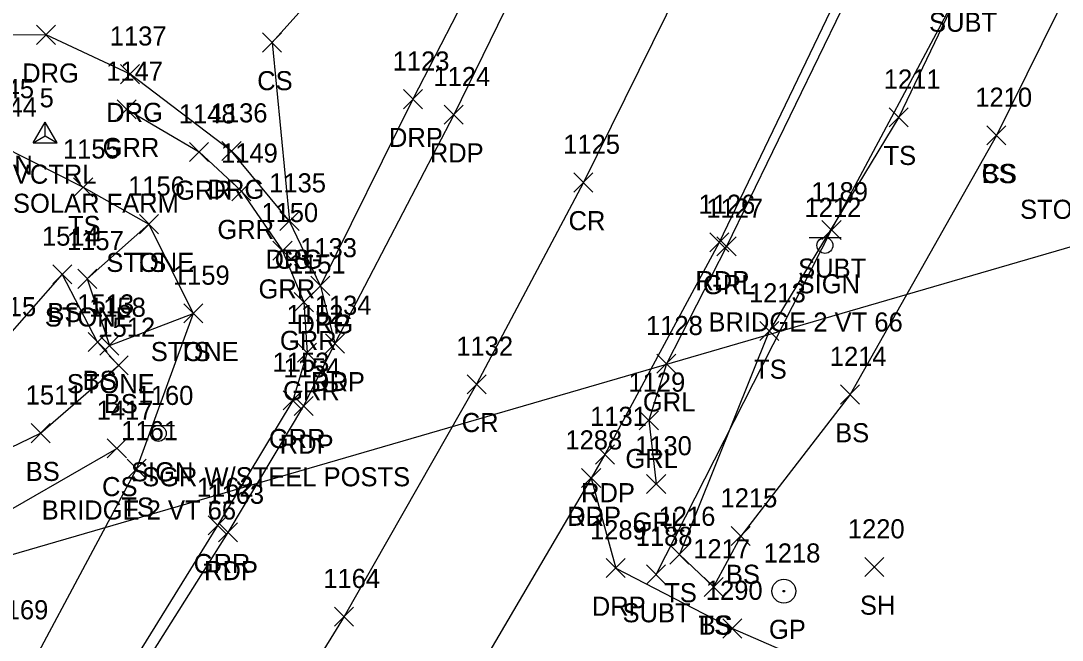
# Model space of a CAD drawing. Extents: x 1599840 to 1601211, y 518904 to 521989.
# Drawn here: x 1600815 to 1600924.1, y 521288.6 to 521353.5 of the extents above; entities that cross this region are included whole.
import ezdxf

# ---------------------------------------------------------------- set-up
doc = ezdxf.new("R2010")
doc.units = 0
for name, color, linetype in [('C_A', 7, 'Continuous'), ('C_I', 7, 'Continuous'), ('CPSM', 7, 'Continuous'), ('DCP', 7, 'Continuous'), ('L_A', 7, 'Continuous'), ('L_C', 7, 'Continuous'), ('L_I', 7, 'Continuous'), ('L_TIC', 7, 'Continuous'), ('LASF', 7, 'Continuous'), ('LELB', 7, 'Continuous'), ('P_A', 7, 'Continuous'), ('P_I', 7, 'Continuous'), ('P_TIC', 7, 'Continuous'), ('PET', 7, 'Continuous'), ('PRC', 7, 'Continuous'), ('R_A', 7, 'Continuous'), ('R_C', 7, 'Continuous'), ('R_I', 7, 'Continuous'), ('R_TIC', 7, 'Continuous'), ('RDG', 7, 'Continuous'), ('RDP', 7, 'Continuous'), ('RGP', 7, 'Continuous'), ('RGR', 7, 'Continuous'), ('S_A', 7, 'Continuous'), ('S_C', 7, 'Continuous'), ('S_I', 7, 'Continuous'), ('SSGN', 7, 'Continuous'), ('U_A', 7, 'Continuous'), ('U_I', 7, 'Continuous'), ('U_TIC', 7, 'Continuous'), ('UT', 7, 'Continuous')]:
    doc.layers.add(name, color=color, linetype=linetype)

msp = doc.modelspace()

# ---------------------------------------------------------------- linework, layer by layer
at = {"layer": 'CPSM'}
for p, q in [((1600816.3, 521340.7), (1600817.55, 521342.87)), ((1600818.8, 521340.7), (1600817.55, 521342.87)), ((1600817.55, 521341.42), (1600817.55, 521342.87)), ((1600816.3, 521340.7), (1600817.55, 521341.42)), ((1600817.55, 521341.42), (1600817.55, 521341.42)), ((1600817.55, 521341.42), (1600818.8, 521340.7)), ((1600816.3, 521340.7), (1600818.8, 521340.7))]:
    msp.add_line(p, q, dxfattribs=at)
at = {"layer": 'DCP'}
msp.add_lwpolyline([(1600954.73, 521338.43), (1600785.44, 521289.23)], dxfattribs=at)
at = {"layer": 'L_TIC'}
for points in [[(1600840.34, 521350.21), (1600842.34, 521352.21)], [(1600842.34, 521350.21), (1600840.34, 521352.21)], [(1600906.01, 521342.38), (1600908.01, 521344.38)], [(1600908.01, 521342.38), (1600906.01, 521344.38)], [(1600916.25, 521340.48), (1600918.25, 521342.48)], [(1600918.25, 521340.48), (1600916.25, 521342.48)], [(1600916.25, 521340.48), (1600918.25, 521342.48)], [(1600918.25, 521340.48), (1600916.25, 521342.48)], [(1600820.54, 521335.05), (1600822.54, 521337.05)], [(1600822.54, 521335.05), (1600820.54, 521337.05)], [(1600827.43, 521331.18), (1600829.43, 521333.18)], [(1600829.43, 521331.18), (1600827.43, 521333.18)], [(1600827.43, 521331.18), (1600829.43, 521333.18)], [(1600829.43, 521331.18), (1600827.43, 521333.18)], [(1600827.43, 521331.18), (1600829.43, 521333.18)], [(1600829.43, 521331.18), (1600827.43, 521333.18)], [(1600842.17, 521331.51), (1600844.17, 521333.51)], [(1600844.17, 521331.51), (1600842.17, 521333.51)], [(1600818.35, 521325.93), (1600820.35, 521327.93)], [(1600820.35, 521325.93), (1600818.35, 521327.93)], [(1600820.97, 521325.46), (1600822.97, 521327.46)], [(1600822.97, 521325.46), (1600820.97, 521327.46)], [(1600832.08, 521321.84), (1600834.08, 521323.84)], [(1600834.08, 521321.84), (1600832.08, 521323.84)], [(1600832.08, 521321.84), (1600834.08, 521323.84)], [(1600834.08, 521321.84), (1600832.08, 521323.84)], [(1600832.08, 521321.84), (1600834.08, 521323.84)], [(1600834.08, 521321.84), (1600832.08, 521323.84)], [(1600892.45, 521319.99), (1600894.45, 521321.99)], [(1600894.45, 521319.99), (1600892.45, 521321.99)], [(1600822.05, 521318.83), (1600824.05, 521320.83)], [(1600824.05, 521318.83), (1600822.05, 521320.83)], [(1600823.29, 521318.48), (1600825.29, 521320.48)], [(1600825.29, 521318.48), (1600823.29, 521320.48)], [(1600824.26, 521316.39), (1600826.26, 521318.39)], [(1600826.26, 521316.39), (1600824.26, 521318.39)], [(1600900.91, 521313.34), (1600902.91, 521315.34)], [(1600902.91, 521313.34), (1600900.91, 521315.34)], [(1600816.08, 521309.29), (1600818.08, 521311.29)], [(1600818.08, 521309.29), (1600816.08, 521311.29)], [(1600824.07, 521307.7), (1600826.07, 521309.7)], [(1600826.07, 521307.7), (1600824.07, 521309.7)], [(1600826.14, 521305.56), (1600828.14, 521307.56)], [(1600828.14, 521305.56), (1600826.14, 521307.56)], [(1600889.46, 521298.52), (1600891.46, 521300.52)], [(1600891.46, 521298.52), (1600889.46, 521300.52)], [(1600883.03, 521296.59), (1600885.03, 521298.59)], [(1600885.03, 521296.59), (1600883.03, 521298.59)], [(1600903.46, 521295.28), (1600905.46, 521297.28)], [(1600905.46, 521295.28), (1600903.46, 521297.28)], [(1600886.61, 521293.19), (1600888.61, 521295.19)], [(1600888.61, 521293.19), (1600886.61, 521295.19)], [(1600886.61, 521293.19), (1600888.61, 521295.19)], [(1600888.61, 521293.19), (1600886.61, 521295.19)]]:
    msp.add_lwpolyline(points, dxfattribs=at)
at = {"layer": 'LASF'}
for points in [[(1600828.43, 521332.18), (1600821.97, 521326.46), (1600824.29, 521319.48), (1600833.08, 521322.84)], [(1600828.43, 521332.18), (1600833.08, 521322.84)]]:
    msp.add_lwpolyline(points, dxfattribs=at)
at = {"layer": 'LELB'}
for points in [[(1600966.09, 521495.52), (1600959.78, 521473.28), (1600948.85, 521440.97), (1600941.09, 521418.3), (1600930.04, 521391.16), (1600917.79, 521365.83), (1600907.01, 521343.38), (1600893.45, 521320.99), (1600884.03, 521297.59), (1600887.61, 521294.19)], [(1600939.06, 521387.92), (1600926.77, 521360.7), (1600917.25, 521341.48)], [(1600849.45, 521360.23), (1600841.34, 521351.21), (1600843.17, 521332.51)], [(1600917.25, 521341.48), (1600901.91, 521314.34), (1600890.46, 521299.52), (1600887.61, 521294.19)], [(1600756.56, 521333.97), (1600770.61, 521339.96), (1600790.38, 521340.53), (1600812.86, 521340.45), (1600821.54, 521336.05), (1600828.43, 521332.18)], [(1600806.43, 521305.18), (1600817.08, 521310.29), (1600825.26, 521317.39), (1600823.05, 521319.83), (1600819.35, 521326.93), (1600812.8, 521319.54), (1600805.24, 521316.79)], [(1600833.08, 521322.84), (1600827.14, 521306.56), (1600810.92, 521276.32), (1600800.69, 521262.52), (1600794.58, 521254.04), (1600785.73, 521239.52), (1600767.25, 521213.82), (1600747.49, 521193.49), (1600721.35, 521163.12)], [(1600741.13, 521196.94), (1600761, 521225.76), (1600770.64, 521247.14), (1600790.98, 521265.75), (1600800.28, 521274.95), (1600804.56, 521287.9), (1600802.13, 521291.13), (1600804.08, 521295.26), (1600810.48, 521300.32), (1600825.07, 521308.7)]]:
    msp.add_lwpolyline(points, dxfattribs=at)
at = {"layer": 'P_TIC'}
for points in [[(1600859.38, 521342.64), (1600861.38, 521344.64)], [(1600861.38, 521342.64), (1600859.38, 521344.64)], [(1600872.97, 521335.55), (1600874.97, 521337.55)], [(1600874.97, 521335.55), (1600872.97, 521337.55)], [(1600887.21, 521329.27), (1600889.21, 521331.27)], [(1600889.21, 521329.27), (1600887.21, 521331.27)], [(1600846.93, 521318.69), (1600848.93, 521320.69)], [(1600848.93, 521318.69), (1600846.93, 521320.69)], [(1600861.78, 521314.41), (1600863.78, 521316.41)], [(1600863.78, 521314.41), (1600861.78, 521316.41)], [(1600843.65, 521312.14), (1600845.65, 521314.14)], [(1600845.65, 521312.14), (1600843.65, 521314.14)], [(1600875.23, 521307.06), (1600877.23, 521309.06)], [(1600877.23, 521307.06), (1600875.23, 521309.06)], [(1600873.78, 521304.59), (1600875.78, 521306.59)], [(1600875.78, 521304.59), (1600873.78, 521306.59)], [(1600835.72, 521298.9), (1600837.72, 521300.9)], [(1600837.72, 521298.9), (1600835.72, 521300.9)], [(1600847.88, 521290.08), (1600849.88, 521292.08)], [(1600849.88, 521290.08), (1600847.88, 521292.08)]]:
    msp.add_lwpolyline(points, dxfattribs=at)
at = {"layer": 'PET'}
for points in [[(1600925.83, 521507.52), (1600915.18, 521473.31), (1600903.26, 521440.28), (1600887.48, 521401.44), (1600873.35, 521370.15), (1600860.38, 521343.64), (1600847.93, 521319.69), (1600844.65, 521313.14), (1600836.72, 521299.9), (1600818.79, 521271.51), (1600793.69, 521233.92), (1600774.49, 521208.06), (1600757.09, 521185.54), (1600730.91, 521154.49)], [(1600955.79, 521499.34), (1600943.51, 521460.9), (1600932.49, 521430.95), (1600915.63, 521388.21), (1600902.46, 521359.92), (1600888.21, 521330.27), (1600876.23, 521308.06), (1600874.78, 521305.59), (1600851.3, 521265.61), (1600837.44, 521243.85), (1600825.08, 521225.62), (1600799.95, 521190.82), (1600794.12, 521183.15), (1600773.8, 521157.79), (1600751.79, 521131.81)]]:
    msp.add_lwpolyline(points, dxfattribs=at)
at = {"layer": 'PRC'}
msp.add_lwpolyline([(1600941.11, 521503.3), (1600929.22, 521466.1), (1600917.95, 521435.49), (1600901.05, 521394.76), (1600888.43, 521365.83), (1600873.97, 521336.55), (1600862.78, 521315.41), (1600848.88, 521291.08), (1600831.54, 521262.94), (1600805.42, 521224.44), (1600786.95, 521198.81), (1600768.67, 521175.32), (1600742.32, 521144.02)], dxfattribs=at)
at = {"layer": 'R_TIC'}
for points in [[(1600816.66, 521351.01), (1600818.66, 521353.01)], [(1600818.66, 521351.01), (1600816.66, 521353.01)], [(1600825.46, 521346.89), (1600827.46, 521348.89)], [(1600827.46, 521346.89), (1600825.46, 521348.89)], [(1600855.1, 521344.27), (1600857.1, 521346.27)], [(1600857.1, 521344.27), (1600855.1, 521346.27)], [(1600825.09, 521343.21), (1600827.09, 521345.21)], [(1600827.09, 521343.21), (1600825.09, 521345.21)], [(1600832.69, 521338.74), (1600834.69, 521340.74)], [(1600834.69, 521338.74), (1600832.69, 521340.74)], [(1600836.09, 521338.84), (1600838.09, 521340.84)], [(1600838.09, 521338.84), (1600836.09, 521340.84)], [(1600837.12, 521334.63), (1600839.12, 521336.63)], [(1600839.12, 521334.63), (1600837.12, 521336.63)], [(1600842.17, 521331.51), (1600844.17, 521333.51)], [(1600844.17, 521331.51), (1600842.17, 521333.51)], [(1600887.96, 521328.85), (1600889.96, 521330.85)], [(1600889.96, 521328.85), (1600887.96, 521330.85)], [(1600841.43, 521328.4), (1600843.43, 521330.4)], [(1600843.43, 521328.4), (1600841.43, 521330.4)], [(1600845.4, 521324.72), (1600847.4, 521326.72)], [(1600847.4, 521324.72), (1600845.4, 521326.72)], [(1600845.4, 521324.72), (1600847.4, 521326.72)], [(1600847.4, 521324.72), (1600845.4, 521326.72)], [(1600843.67, 521323.01), (1600845.67, 521325.01)], [(1600845.67, 521323.01), (1600843.67, 521325.01)], [(1600846.93, 521318.69), (1600848.93, 521320.69)], [(1600848.93, 521318.69), (1600846.93, 521320.69)], [(1600844, 521317.73), (1600846, 521319.73)], [(1600846, 521317.73), (1600844, 521319.73)], [(1600881.66, 521316.57), (1600883.66, 521318.57)], [(1600883.66, 521316.57), (1600881.66, 521318.57)], [(1600842.51, 521312.73), (1600844.51, 521314.73)], [(1600844.51, 521312.73), (1600842.51, 521314.73)], [(1600879.82, 521310.64), (1600881.82, 521312.64)], [(1600881.82, 521310.64), (1600879.82, 521312.64)], [(1600873.78, 521304.59), (1600875.78, 521306.59)], [(1600875.78, 521304.59), (1600873.78, 521306.59)], [(1600880.59, 521303.98), (1600882.59, 521305.98)], [(1600882.59, 521303.98), (1600880.59, 521305.98)], [(1600834.63, 521299.64), (1600836.63, 521301.64)], [(1600836.63, 521299.64), (1600834.63, 521301.64)], [(1600876.36, 521295.17), (1600878.36, 521297.17)], [(1600878.36, 521295.17), (1600876.36, 521297.17)], [(1600888.58, 521288.84), (1600890.58, 521290.84)], [(1600890.58, 521288.84), (1600888.58, 521290.84)]]:
    msp.add_lwpolyline(points, dxfattribs=at)
at = {"layer": 'RDG'}
msp.add_lwpolyline([(1600846.4, 521325.72), (1600843.17, 521332.51), (1600837.09, 521339.84), (1600826.46, 521347.89), (1600817.66, 521352.01), (1600799.49, 521351.98), (1600769.3, 521346.82)], dxfattribs=at)
at = {"layer": 'RDP'}
for points in [[(1600873.35, 521370.15), (1600867.81, 521367.99), (1600856.1, 521345.27), (1600846.4, 521325.72), (1600847.93, 521319.69)], [(1600874.78, 521305.59), (1600877.36, 521296.17), (1600889.58, 521289.84), (1600907.97, 521281.86), (1600920.96, 521276.4), (1600937.85, 521271.62)]]:
    msp.add_lwpolyline(points, dxfattribs=at)
at = {"layer": 'RGP'}
msp.add_line((1600894.97, 521293.75), (1600894.97, 521293.75), dxfattribs=at)
for radius in [1.25, 0.0833]:
    msp.add_circle((1600894.97, 521293.75), radius, dxfattribs=at)
at = {"layer": 'RGR'}
for points in [[(1600956.84, 521499.16), (1600944.35, 521460.55), (1600933.48, 521430.45), (1600916.49, 521387.81), (1600903.42, 521359.61), (1600888.96, 521329.85), (1600882.66, 521317.57), (1600880.82, 521311.64), (1600881.59, 521304.98)], [(1600826.09, 521344.21), (1600833.69, 521339.74), (1600838.12, 521335.63), (1600842.43, 521329.4), (1600844.67, 521324.01), (1600845, 521318.73), (1600843.51, 521313.73), (1600835.63, 521300.64), (1600817.84, 521271.9), (1600810.24, 521260.24), (1600806.53, 521256.68), (1600802.26, 521254.42), (1600799.01, 521253.84)]]:
    msp.add_lwpolyline(points, dxfattribs=at)
at = {"layer": 'SSGN'}
for p, q in [((1600897.64, 521330.79), (1600900.97, 521330.79)), ((1600899.28, 521329.96), (1600899.28, 521329.96)), ((1600827.77, 521311.11), (1600831.1, 521311.11)), ((1600829.42, 521310.27), (1600829.42, 521310.27))]:
    msp.add_line(p, q, dxfattribs=at)
for centre in [(1600899.28, 521329.96), (1600829.42, 521310.27)]:
    msp.add_circle(centre, 0.833, dxfattribs=at)
at = {"layer": 'U_TIC'}
for points in [[(1600898.97, 521330.58), (1600900.97, 521332.58)], [(1600900.97, 521330.58), (1600898.97, 521332.58)], [(1600880.58, 521294.49), (1600882.58, 521296.49)], [(1600882.58, 521294.49), (1600880.58, 521296.49)]]:
    msp.add_lwpolyline(points, dxfattribs=at)
at = {"layer": 'UT'}
msp.add_lwpolyline([(1600881.58, 521295.49), (1600899.97, 521331.58), (1600913.69, 521357.33)], dxfattribs=at)

# ---------------------------------------------------------------- texts
at = {"layer": 'C_A'}
msp.add_text('HVCTRL', height=2, dxfattribs=at).set_placement((1600812.24, 521336.42))
at = {"layer": 'C_I'}
msp.add_text('5', height=2, dxfattribs=at).set_placement((1600816.98, 521344.42))
at = {"layer": 'L_A'}
for s, p in [('CS', (1600839.78, 521346.21)), ('TS', (1600905.42, 521338.38)), ('CS', (1600915.69, 521336.48)), ('BS', (1600915.69, 521336.48)), ('TS', (1600819.95, 521331.05)), ('CS', (1600841.61, 521327.51)), ('STONE', (1600823.97, 521327.18)), ('STONE', (1600823.97, 521327.18)), ('TS', (1600826.84, 521327.18)), ('BS', (1600817.79, 521321.93)), ('STONE', (1600817.52, 521321.46)), ('STONE', (1600828.63, 521317.84)), ('STONE', (1600828.63, 521317.84)), ('TS', (1600831.49, 521317.84)), ('TS', (1600891.86, 521315.99)), ('STONE', (1600819.83, 521314.48)), ('BS', (1600821.49, 521314.83)), ('BS', (1600823.7, 521312.39)), ('BS', (1600900.35, 521309.34)), ('BS', (1600815.52, 521305.29)), ('CS', (1600823.52, 521303.7)), ('TS', (1600825.55, 521301.56)), ('BS', (1600888.9, 521294.52)), ('TS', (1600882.44, 521292.59)), ('SH', (1600902.95, 521291.28)), ('TS', (1600886.02, 521289.19)), ('BS', (1600886.05, 521289.19))]:
    msp.add_text(s, height=2, dxfattribs=at).set_placement(p)
at = {"layer": 'L_C'}
msp.add_text('STONE LAID UP ALONG PIPE CUT ON', height=2, dxfattribs=at).set_placement((1600919.73, 521332.74))
at = {"layer": 'L_I'}
for s, p in [('1211', (1600905.45, 521346.38)), ('1210', (1600915.04, 521344.48)), ('1210', (1600915.04, 521344.48)), ('1144', (1600810.74, 521343.45)), ('1155', (1600819.42, 521339.05)), ('1156', (1600826.25, 521335.18)), ('1156', (1600826.25, 521335.18)), ('1156', (1600826.25, 521335.18)), ('1135', (1600841.04, 521335.51)), ('1514', (1600817.23, 521329.93)), ('1157', (1600819.85, 521329.46)), ('1159', (1600830.95, 521325.84)), ('1159', (1600830.95, 521325.84)), ('1159', (1600830.95, 521325.84)), ('1213', (1600891.32, 521323.99)), ('1515', (1600810.67, 521322.54)), ('1513', (1600820.93, 521322.83)), ('1158', (1600822.16, 521322.48)), ('1512', (1600823.14, 521320.39)), ('1214', (1600899.79, 521317.34)), ('1511', (1600815.52, 521313.29)), ('1417', (1600822.95, 521311.7)), ('1161', (1600825.53, 521309.56)), ('1215', (1600888.34, 521302.52)), ('1216', (1600881.85, 521300.59)), ('1220', (1600901.68, 521299.28)), ('1217', (1600885.48, 521297.19)), ('1217', (1600885.48, 521297.19))]:
    msp.add_text(s, height=2, dxfattribs=at).set_placement(p)
at = {"layer": 'P_A'}
for s, p in [('RDP', (1600857.87, 521338.64)), ('CR', (1600872.41, 521331.55)), ('RDP', (1600885.7, 521325.27)), ('RDP', (1600845.42, 521314.69)), ('CR', (1600861.21, 521310.41)), ('RDP', (1600842.14, 521308.14)), ('RDP', (1600873.72, 521303.06)), ('RDP', (1600872.26, 521300.59)), ('RDP', (1600834.21, 521294.9))]:
    msp.add_text(s, height=2, dxfattribs=at).set_placement(p)
at = {"layer": 'P_I'}
for s, p in [('1124', (1600858.25, 521346.64)), ('1125', (1600871.85, 521339.55)), ('1126', (1600886.03, 521333.27)), ('1134', (1600845.81, 521322.69)), ('1132', (1600860.65, 521318.41)), ('1154', (1600842.53, 521316.14)), ('1131', (1600874.67, 521311.06)), ('1288', (1600872.08, 521308.59)), ('1163', (1600834.55, 521302.9)), ('1164', (1600846.71, 521294.08))]:
    msp.add_text(s, height=2, dxfattribs=at).set_placement(p)
at = {"layer": 'R_A'}
for s, p in [('DRG', (1600815.15, 521347.01)), ('DRG', (1600823.95, 521342.89)), ('DRP', (1600853.59, 521340.27)), ('GRR', (1600823.58, 521339.21)), ('GRR', (1600831.18, 521334.74)), ('DRG', (1600834.58, 521334.84)), ('GRR', (1600835.61, 521330.63)), ('DRG', (1600840.66, 521327.51)), ('GRR', (1600839.92, 521324.4)), ('GRL', (1600886.5, 521324.85)), ('DRG', (1600843.89, 521320.72)), ('DRP', (1600843.89, 521320.72)), ('GRR', (1600842.16, 521319.01)), ('DRP', (1600845.42, 521314.69)), ('GRR', (1600842.49, 521313.73)), ('GRL', (1600880.2, 521312.57)), ('GRR', (1600841, 521308.73)), ('GRL', (1600878.37, 521306.64)), ('DRP', (1600872.26, 521300.59)), ('GRL', (1600879.13, 521299.98)), ('GRR', (1600833.12, 521295.64)), ('DRP', (1600874.85, 521291.17)), ('GP', (1600893.41, 521288.75))]:
    msp.add_text(s, height=2, dxfattribs=at).set_placement(p)
at = {"layer": 'R_C'}
msp.add_text('SGR W/STEEL POSTS', height=2, dxfattribs=at).set_placement((1600827.72, 521304.73))
at = {"layer": 'R_I'}
for s, p in [('1137', (1600824.33, 521350.89)), ('1123', (1600853.98, 521348.27)), ('1147', (1600823.96, 521347.21)), ('1148', (1600831.57, 521342.74)), ('1136', (1600834.91, 521342.84)), ('1149', (1600835.99, 521338.63)), ('1135', (1600841.04, 521335.51)), ('1127', (1600886.84, 521332.85)), ('1150', (1600840.22, 521332.4)), ('1133', (1600844.28, 521328.72)), ('1133', (1600844.28, 521328.72)), ('1151', (1600843.11, 521327.01)), ('1134', (1600845.81, 521322.69)), ('1152', (1600842.87, 521321.73)), ('1128', (1600880.53, 521320.57)), ('1153', (1600841.39, 521316.73)), ('1129', (1600878.69, 521314.64)), ('1288', (1600872.08, 521308.59)), ('1130', (1600879.38, 521307.98)), ('1162', (1600833.46, 521303.64)), ('1289', (1600874.66, 521299.17)), ('1218', (1600892.85, 521296.75)), ('1290', (1600886.8, 521292.84))]:
    msp.add_text(s, height=2, dxfattribs=at).set_placement(p)
at = {"layer": 'S_A'}
for p in [(1600809.72, 521337.37), (1600896.42, 521324.94), (1600826.56, 521305.25)]:
    msp.add_text('SIGN', height=2, dxfattribs=at).set_placement(p)
at = {"layer": 'S_C'}
for s, p in [('INNER TRADITION SOLAR FARM', (1600789.97, 521333.37)), ('BRIDGE 2 VT 66', (1600887.07, 521320.94)), ('BRIDGE 2 VT 66', (1600817.2, 521301.25))]:
    msp.add_text(s, height=2, dxfattribs=at).set_placement(p)
at = {"layer": 'S_I'}
for s, p in [('1145', (1600810.44, 521345.37)), ('1212', (1600897.14, 521332.94)), ('1160', (1600827.14, 521313.25))]:
    msp.add_text(s, height=2, dxfattribs=at).set_placement(p)
at = {"layer": 'U_A'}
for p in [(1600910.19, 521352.33), (1600896.47, 521326.58), (1600878.07, 521290.49)]:
    msp.add_text('SUBT', height=2, dxfattribs=at).set_placement(p)
at = {"layer": 'U_I'}
for s, p in [('1189', (1600897.84, 521334.58)), ('1188', (1600879.45, 521298.49)), ('1169', (1600811.94, 521290.8))]:
    msp.add_text(s, height=2, dxfattribs=at).set_placement(p)

doc.saveas('drawing.dxf')
